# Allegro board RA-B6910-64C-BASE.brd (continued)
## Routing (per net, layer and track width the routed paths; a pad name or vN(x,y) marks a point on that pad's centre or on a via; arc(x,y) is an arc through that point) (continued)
FAN0_SDA: length 236.5
  TOP w0.201: v2(96.74,158.53) 96,157.79 96,156.87 96.33,156.54 R227.2 96.99,156.54 97.27,156.26 97.27,152.83 97.6,152.5 97.6,151.79 97.37,151.56 U8.4
  SIG2 w0.16: J2.13 309.61,165.28 304.03,165.28 303.05,166.26 217.94,166.26 214.48,162.8 182.87,162.8 180.13,165.55 157.77,165.55 156,167.32 145.61,167.32 144.23,165.95 139.03,165.95 129.38,156.3 123.89,156.3 121.4,158.79 112.25,158.79 111.43,157.97 97.85,157.97 97.3,158.53 v2(96.74,158.53)
FAN0_TACH: length 218.9
  TOP w0.201: Q11.3 132.93,120.2 132.55,120.58 R277.2 131.66,120.68 132.62,121.63 132.62,124.86 v1(132.77,125.01) 132.97,125.21 U1.33 ; R311.2 v2(314.72,166.32)
  SIG1 w0.15: v2(314.72,166.32) 311.96,166.32 293.82,148.18 166.32,148.18 143.93,125.79 133.55,125.79 v1(132.77,125.01)
FAN0_TACH_RESERVE: length 11.1
  TOP w0.508: v2(327.01,170.74) R331.1 R329.1 328.18,172.49 328.16,172.52 R330.1
  SIG1 w0.508: v2(327.01,170.74) 324.68,168.41 J2.16
FAN0_TACH_RESERVE_CPLD: length 224
  TOP w0.201: U1.76 v1(132.97,147.26)
  TOP w0.508: R330.2 R328.2 331.74,174.02 332.22,173.54 Q14.3 v2(331.08,172.65)
  SIG2 w0.508: v1(132.97,147.26) 132.97,147.38 139.96,154.36 139.96,155.75 150.01,165.81 155.37,165.81 157.14,164.04 179.49,164.04 182.24,161.29 206.03,161.29 206.77,160.55 211.94,160.55 212.68,161.29 215.11,161.29 218.57,164.75 302.27,164.75 305.35,161.67 316.17,161.67 326.25,171.76 330.19,171.76 v2(331.08,172.65)
FAN1_E2_WP: length 119.3
  TOP w0.201: R6.2 v2(123.56,122.74)
  SIG1 w0.15: J4.6 210.94,169.53 210.94,163.12 211.71,162.35 211.71,161.54 203.05,152.88 165.13,152.88 143.9,131.65 130.95,131.65 129.15,129.84 124.57,129.84 122.93,128.2 122.93,124.39 123.56,123.75 v2(123.56,122.74)
FAN1_EN: length 122.9
  TOP w0.201: R326.2 125.97,122.23 v2(125.85,122.1) 125.57,121.82 R339.1
  SIG1 w0.15: v2(125.85,122.1) 125.73,122.21 125.73,125.11 126.27,125.64 126.27,126.33 127.83,127.9 128.81,127.9 131.42,130.51 144.37,130.51 165.29,151.43 203.39,151.43 219.27,167.31 220.46,167.31 221.22,168.07 221.22,169.65 J4.2
FAN1_LED1: length 114
  TOP w0.201: v2(123.94,128.45) 123.47,127.98 U1.14
  SIG1 w0.15: v2(123.94,128.45) 124.96,129.47 129.31,129.47 131.11,131.27 144.05,131.27 165.19,152.41 203.12,152.41 213.48,162.77 213.48,169.53 J4.5
FAN1_LED2: length 108.8
  TOP w0.201: v2(126.86,128.45) 126.47,128.06 U1.20
  SIG1 w0.15: J4.12 214.9,163.66 203.18,151.94 165.26,151.94 144.21,130.89 131.27,130.89 128.83,128.45 v2(126.86,128.45)
FAN1_POWER_OK#: length 137.4
  TOP w0.201: v2(128.02,130.81) 127.98,130.77 127.98,128.42 127.97,128.41 U1.23 127.97,125.34 R164.1 ; R100.1 240.38,169.22 240.52,169.08 240.52,166.59 239.42,165.49 214.7,165.49 212.84,163.63 210.86,163.63 v1(208.56,161.33)
  SIG1 w0.15: v2(128.02,130.81) 130.15,132.95 135.83,132.95 136.6,133.71 144.89,133.71 165.09,153.91 201.14,153.91 v1(208.56,161.33)
FAN1_PRESENT_IN#: length 136.2
  TOP w0.201: v1(129.28,130.74) 129.28,129.4 128.47,128.6 U1.24 128.47,125.1 128.13,124.77 R163.1 ; R99.1 241.06,166.42 239.63,164.98 215.72,164.98 213.86,163.13 211.38,163.13 v2(209.6,161.34)
  SIG1 w0.15: v2(209.6,161.34) 201.61,153.35 165.06,153.35 145.05,133.34 136.76,133.34 135.99,132.57 131.11,132.57 v1(129.28,130.74)
FAN1_PWM: length 114.2
  TOP w0.201: U1.21 v2(126.97,126.02)
  SIG1 w0.15: v2(126.97,126.02) 127.46,126.02 131.58,130.13 144.53,130.13 165.31,150.92 203.42,150.92 219.43,166.93 221.04,166.93 J4.15
FAN1_SCL: length 148.7
  TOP w0.201: v2(97.85,159.18) 97.22,159.82 94.35,159.82 93.59,159.06 93.59,156.9 94.12,156.37 94.12,154.21 94.45,153.88 R230.2 94.99,153.27 95.57,152.69 95.57,151.89 95.42,151.75 U8.7
  SIG2 w0.16: J4.4 218.68,169.71 218.68,167.95 214.21,163.47 183.16,163.47 180.41,166.22 158.04,166.22 156.27,167.99 145.33,167.99 143.96,166.62 138.76,166.62 129.1,156.96 124.17,156.96 121.67,159.46 106.73,159.46 105.91,158.64 98.39,158.64 v2(97.85,159.18)
FAN1_SDA: length 143.6
  TOP w0.201: v2(94.35,157.91) 94.35,157.18 94.99,156.54 R229.2 95.6,156.54 96,156.14 96,154.99 95.75,154.74 95.75,153.47 96,153.22 96,151.95 96.07,151.87 U8.6
  SIG2 w0.16: v2(94.35,157.91) 93.97,158.3 93.97,159.48 94.31,159.82 98.16,159.82 98.67,159.31 105.63,159.31 106.45,160.13 121.95,160.13 124.45,157.63 128.83,157.63 138.48,167.28 143.68,167.28 145.05,168.65 156.55,168.65 158.32,166.88 180.71,166.88 183.45,164.14 213.17,164.14 J4.13
FAN1_TACH: length 136.7
  TOP w0.201: v1(126.75,130.81) 127.47,130.09 U1.22 ; R312.2 239.87,166.65 239.51,166.3 233.16,166.3 232.78,166.68 Q12.3 231.23,168.07 230.85,167.69 R280.2 230.85,166.42 230.42,165.99 214.49,165.99 212.63,164.14 210.35,164.14 v2(207.52,161.31)
  SIG1 w0.15: v2(207.52,161.31) 200.5,154.29 164.93,154.29 144.74,134.09 129.79,134.09 126.75,131.05 v1(126.75,130.81)
FAN1_TACH_RESERVE: length 12.7
  TOP w0.508: v2(232.4,173.54) R349.1 R347.1 233.31,175.29 233.29,175.31 R348.1
  SIG1 w0.508: v2(232.4,173.54) 227.27,168.41 J4.16
FAN1_TACH_RESERVE_CPLD: length 130
  TOP w0.201: v1(133.97,147.25) 133.47,147.75 U1.75
  TOP w0.508: R348.2 R346.2 236.74,176.81 237.35,176.2 Q15.3 v2(236.08,175.44)
  SIG1 w0.508: v2(236.08,175.44) 236.08,175.13 230.62,169.67 230.62,165.92 229.86,165.15 v1(229.86,163.88)
  SIG2 w0.508: v1(229.86,163.88) 218.76,163.88 215.42,160.54 212.99,160.54 212.25,159.8 206.46,159.8 205.72,160.54 181.93,160.54 179.18,163.29 156.83,163.29 155.06,165.06 150.32,165.06 140.71,155.44 140.71,154.05 133.97,147.32 v1(133.97,147.25)
FAN2_E2_WP: length 98.3
  TOP w0.201: R31.2 117.95,123.4 117.82,123.52 v2(117.82,123.95)
  SIG1 w0.15: J5.6 118.12,172.01 130.29,172.01 131.05,171.25 131.05,163.88 137.42,157.52 138.57,157.52 149.98,146.11 149.98,140.41 146.2,136.63 138.09,136.63 136.51,135.05 122.03,135.05 120.82,133.85 120.82,129.32 119.5,128 119.5,126.28 117.82,124.61 v2(117.82,123.95)
FAN2_EN: length 86.6
  TOP w0.201: R345.1 R325.2 116.8,123.4 116.45,123.75 116.45,124.82 v2(117.02,125.39)
  SIG1 w0.15: J5.2 128.51,169.66 128.51,165.89 137.26,157.14 138.41,157.14 149.59,145.97 149.59,140.55 146.64,137.61 138.13,137.61 136.1,135.57 121.75,135.57 120.12,133.95 120.12,129.16 117.85,126.88 117.85,126.22 v2(117.02,125.39)
FAN2_LED1: length 85.4
  TOP w0.201: v2(118.9,128.58) 118.47,128.15 U1.4
  SIG1 w0.15: v2(118.9,128.58) 118.9,129.86 119.37,130.33 119.37,134.26 121.43,136.33 135.78,136.33 137.82,138.36 146.33,138.36 148.83,140.87 148.83,145.65 138.1,156.39 136.95,156.39 127.25,166.09 122.46,166.09 120.89,167.65 120.89,169.66 J5.5
FAN2_LED2: length 82.9
  TOP w0.201: U1.2 117.47,128.2 117.48,128.21 v2(117.48,128.52)
  SIG1 w0.15: v2(117.48,128.52) 117.72,128.77 117.72,129.21 118.99,130.48 118.99,134.42 121.28,136.71 135.63,136.71 137.66,138.74 146.17,138.74 148.45,141.02 148.45,145.5 137.94,156.01 136.79,156.01 127.09,165.71 122.3,165.71 J5.12
FAN2_POWER_OK#: length 38.9
  TOP w0.201: R103.1 111.24,154.39 113.18,152.45 113.18,150.13 114.58,148.73 115.48,148.73 122.77,141.44 v1(122.77,130.12) 121.47,128.83 U1.10 121.47,126.3 121.02,125.85 R167.1
  BOTTOM w0.201: v3(123.7,130.05) 122.84,130.05 v1(122.77,130.12)
FAN2_PRESENT_IN#: length 42.8
  TOP w0.201: R166.1 119.52,121.82 119.12,122.23 119.12,125.78 119.47,126.14 U1.6 119.47,129.01 v1(121.4,130.95) 121.76,131.3 121.76,141.02 115.12,147.65 114.23,147.65 112,149.88 112,152.2 109.21,154.99 R102.1
  BOTTOM w0.201: v1(121.4,130.95) 120.9,131.44 v3(120.52,131.44)
FAN2_PWM: length 78.6
  TOP w0.201: U1.1 116.97,128.65 118.04,129.72 v2(119.5,129.72)
  SIG1 w0.15: J5.15 127.22,166.65 137.1,156.76 138.26,156.76 149.21,145.81 149.21,140.71 146.49,137.99 137.98,137.99 135.94,135.95 121.59,135.95 119.75,134.11 119.75,129.97 v2(119.5,129.72)
FAN2_SCL: length 50.3
  TOP w0.201: v2(90.29,154.46) 90.87,153.88 R232.2 92.7,152.83 94.12,151.41 U8.9
  SIG2 w0.16: v2(90.29,154.46) 89.52,155.22 89.52,159.48 93.45,163.41 103.08,163.41 105.08,165.41 116.32,165.41 118.35,167.44 118.35,169.34 118.8,169.79 120.2,169.79 121.36,170.95 J5.4
FAN2_SDA: length 47.7
  TOP w0.201: U8.8 94.77,152.41 93.41,153.78 93.41,156.06 92.93,156.54 R231.2 90.39,156.54 v2(90.26,156.54)
  SIG2 w0.16: J5.13 118.07,164.34 106.49,164.34 104.89,162.74 93.73,162.74 90.26,159.27 v2(90.26,156.54)
FAN2_TACH: length 46.7
  TOP w0.201: R283.2 110.23,154.69 112.51,152.41 v1(112.51,152.07) 112.51,150.09 114.42,148.18 115.31,148.18 122.26,141.23 122.26,130.71 120.97,129.42 U1.9 ; v2(110.99,152.07) 108.96,154.1 108.07,154.1 107.3,154.87 Q13.3 107.3,157.71 106.46,158.55 R313.2
  SIG1 w0.15: v2(110.99,152.07) v1(112.51,152.07)
FAN2_TACH_RESERVE: length 10.7
  TOP w0.508: R353.1 138.55,165.79 138.52,165.76 R352.1 R354.1 136.77,166.17 v2(135.63,167.31)
  SIG2 w0.508: v2(135.63,167.31) 134.53,168.41 J5.16
FAN2_TACH_RESERVE_CPLD: length 21
  TOP w0.201: U1.74 133.97,149.41 v1(133.47,149.91)
  TOP w0.508: R353.2 R351.2 140.05,162.21 139.56,161.72 Q16.3 v2(138.67,160.71)
  SIG2 w0.508: v2(138.67,160.71) 138.67,157.41 137.91,156.64 137.91,153.87 133.96,149.91 v1(133.47,149.91)
GPIO_I2C_SCL: length 199
  TOP w0.127: U9.B27 v1(163.8,68.15)
  TOP w0.201: R268.1 140.48,132.9 138.85,132.9 137.65,134.1 U1.47 135.03,134.1 133.75,132.82 132.44,132.82 131.62,132 v2(131.62,128.4) ; v1(94.33,90.35) YJ1.A8_1
  SIG2 w0.16: v2(131.62,128.4) 131.62,127.9 130.36,126.64 110.36,126.64 110.05,126.33 103.88,126.33 103.19,125.64 99.46,125.64 98.83,125.01 95.21,125.01 91.54,121.35 89.05,121.35 85.18,117.49 79.58,117.49 73.95,111.86 73.95,100.55 84.16,90.35 v1(94.33,90.35) 97.4,90.35 99.02,88.73 122.82,88.73 139.75,71.81 149.34,71.81 153.85,67.3 162.94,67.3 v1(163.8,68.15)
GPIO_I2C_SDA: length 206.4
  TOP w0.127: U9.B28 v1(165.07,65.61)
  TOP w0.201: YJ1.A7_1 95.58,94.67 95.92,94.33 95.92,90.62 v1(94.99,89.68) ; v2(141.51,132.69) 141.51,132.87 141.37,133.01 R270.1 R269.2
  SIG2 w0.16: v2(141.51,132.69) 138.8,129.97 131.94,129.97 130.95,128.98 130.95,128.18 130.08,127.31 110.1,127.31 109.72,127.69 108.19,127.69 107.61,127.1 103.65,127.1 102.86,126.31 96.54,126.31 95.92,125.68 94.93,125.68 92.6,123.35 84.49,123.35 73.28,112.14 73.28,100.28 83.88,89.68 v1(94.99,89.68) 97.12,89.68 98.74,88.06 122.54,88.06 139.71,70.9 148.83,70.9 153.34,66.39 164.3,66.39 v1(165.07,65.61)
LM75_INT#: length 75.8
  TOP w0.201: R118.1 113.07,130.99 114.18,132.1 U1.138 116.16,132.1 116.45,132.39 116.45,133.03 117.08,133.66 v1(121.27,133.66) ; R221.1 v2(142.67,169.39)
  SIG1 w0.15: v2(142.67,169.39) 142.67,153.95 150.36,146.27 150.36,140.25 144.58,134.47 122.09,134.47 v1(121.27,133.66)
LPC_LAD0: length 93.9
  TOP w0.201: v1(147.19,141.3) 146.93,141.03 146.93,139.5 143.95,136.52 141.65,136.52 141.17,136.05 140.49,136.05 140.39,135.94 R126.2 ; v1(167.37,72.6) U9.A23
  SIG1 w0.15: v2(167.99,125.76) 168.91,124.84 168.91,121.96 169.45,121.42 169.45,74.68 v1(167.37,72.6)
  SIG2 w0.16: v1(147.19,141.3) 152.45,141.3 v2(167.99,125.76)
LPC_LAD0_CPLD: length 119.9
  TOP w0.201: C142.1 89.27,95.94 89.83,95.38 YJ1.A2_1 ; R314.2 144.75,127.94 146.16,126.53 146.16,121.16 v2(133.14,108.13)
  SIG2 w0.16: YJ1.A2_1 89.36,93.27 82.67,99.96 82.67,107.83 86.48,111.64 90.93,111.64 98.45,119.16 101.19,119.16 101.87,119.84 113.04,119.84 124.29,108.59 132.67,108.59 v2(133.14,108.13)
LPC_LAD1: length 95.7
  TOP w0.201: v2(146.15,141.28) 146.15,139.99 143.25,137.09 R129.2 ; U9.A26 v1(167.37,68.79)
  SIG1 w0.15: v1(167.37,68.79) 169.92,71.34 169.92,121.62 v1(169.38,122.16)
  SIG2 w0.16: v2(146.15,141.28) 146.63,141.76 152.64,141.76 168.5,125.89 168.5,123.04 v1(169.38,122.16)
LPC_LAD1_CPLD: length 109
  TOP w0.201: R315.2 144.5,126.93 145.27,126.16 145.27,122.34 v2(131.05,108.13) ; C143.1 78.35,96.95 78.46,97.07 YJ1.B2_1
  SIG2 w0.16: v2(131.05,108.13) 124.18,108.13 113.43,118.88 101.47,118.88 101.36,118.76 98.61,118.76 91.07,111.22 86.65,111.22 83.09,107.66 83.09,103.59 89.61,97.07 YJ1.B2_1
LPC_LAD2: length 102.7
  TOP w0.127: U9.A29 v1(166.34,64.34)
  TOP w0.201: R132.2 140.32,138.23 140.86,138.76 142.51,138.76 144.13,140.39 v1(144.13,141.28)
  SIG1 w0.15: v1(166.34,64.34) 170.39,68.4 170.39,122.93 v2(169.38,123.94)
  SIG2 w0.16: v1(144.13,141.28) 145.02,142.17 152.8,142.17 168.9,126.06 168.9,124.42 v2(169.38,123.94)
LPC_LAD2_CPLD: length 112.2
  TOP w0.201: C144.1 88.45,99.49 YJ1.C2_1 ; v2(133.23,106.72) 133.47,106.72 147.52,120.77 147.52,127.94 145.49,129.97 R316.2
  SIG2 w0.16: v2(133.23,106.72) 132.68,106.17 125,106.17 113.89,117.29 98.28,117.29 91.4,110.42 86.98,110.42 83.89,107.32 83.89,104.23 87.25,100.87 YJ1.C2_1
LPC_LAD3: length 105.7
  TOP w0.127: U9.B30 v1(165.07,63.07)
  TOP w0.201: v2(144.16,142.32) 143.51,141.67 143.51,140.48 142.4,139.37 140.83,139.37 140.71,139.25 R134.2
  SIG1 w0.15: v1(169.38,125.72) 170.86,124.24 170.86,68.18 166.36,63.68 165.68,63.68 v1(165.07,63.07)
  SIG2 w0.16: v2(144.16,142.32) 144.42,142.57 152.96,142.57 169.38,126.15 v1(169.38,125.72)
LPC_LAD3_CPLD: length 114.9
  TOP w0.201: YJ1.B1_1 78.98,98.47 78.48,97.97 C145.1 ; R317.2 145.49,130.99 148.02,128.45 148.02,120.56 133.68,106.22 131.54,106.22 v2(131.05,106.7)
  SIG2 w0.16: v2(131.05,106.7) 125.04,106.7 113.5,118.24 105.79,118.24 105.23,117.69 98.11,117.69 91.24,110.82 86.82,110.82 83.49,107.49 83.49,104.06 YJ1.B1_1
LPC_LCLK: length 76.5
  TOP w0.201: U9.A14 v1(167.37,84.03) ; R136.2 140.58,140.26 140.83,140.52 141.7,140.52 v2(142.21,140.01)
  SIG1 w0.15: v1(166.72,123.99) 166.72,121.84 167.81,120.74 167.81,84.48 v1(167.37,84.03)
  SIG2 w0.16: v2(142.21,140.01) 142.53,139.68 151.86,139.68 166.05,125.49 166.05,124.66 v1(166.72,123.99)
LPC_LCLK_CPLD: length 106.6
  TOP w0.201: R320.2 145.49,132.01 148.71,128.79 148.71,120.53 133.89,105.71 132.06,105.71 v2(131.05,104.7) ; YJ1.C1_1 87.55,100.74 78.21,100.74 77.98,100.51 C146.1
  SIG2 w0.16: v2(131.05,104.7) 125.91,104.7 113.72,116.89 98.44,116.89 88.31,106.75 88.31,104.52 89.08,103.75 YJ1.C1_1
LPC_LFRAME#: length 86.2
  TOP w0.201: R137.2 139.92,141.28 142.55,141.28 v1(143,140.82) ; v1(167.37,76.41) U9.A20
  SIG1 w0.15: v1(167.37,76.41) 168.98,78.02 168.98,121.23 167.99,122.22 v2(167.99,123.98)
  SIG2 w0.16: v2(167.99,123.98) 167.5,124.46 167.5,125.64 152.37,140.77 143.54,140.77 143.48,140.82 v1(143,140.82)
LPC_LFRAME#_CPLD: length 105.1
  TOP w0.201: v2(132.45,104.7) 132.96,105.21 134.1,105.21 149.21,120.32 149.21,129.17 145.36,133.02 R322.2 ; YJ1.D1_1 88.9,105.89 88.9,104.52 86.92,102.54 C147.1
  SIG2 w0.16: YJ1.D1_1 89.08,106.96 98.61,116.49 113.55,116.49 125.8,104.24 131.99,104.24 v2(132.45,104.7)
LPC_SERIRQ: length 83.4
  TOP w0.201: R139.2 142.67,142.29 v2(142.78,142.18) ; U9.A17 v1(167.37,80.22)
  SIG1 w0.15: v1(166.72,125.77) 167.51,124.98 167.51,122.03 168.51,121.03 168.51,81.36 v1(167.37,80.22)
  SIG2 w0.16: v1(166.72,125.77) 166.72,125.77 152.12,140.36 142.8,140.36 142.49,140.67 142.49,141.9 v2(142.78,142.18)
LPC_SERIRQ_CPLD: length 111.4
  TOP w0.201: v2(133.64,104.7) 134.31,104.7 149.72,120.11 149.72,131.12 145.91,134.93 R324.2 ; C148.1 86.69,101.53 YJ1.D2_1
  SIG2 w0.16: YJ1.D2_1 89.83,107.14 98.78,116.08 113.36,116.08 125.61,103.84 132.78,103.84 v2(133.64,104.7)
MDI_0N: length 275.7
  TOP w0.127: U9.A32 v1(166.34,60.53)
  SIG2 w0.104: J10.2 407.04,4.06 407.04,4.74 406.49,5.3 406.49,6.57 406.55,6.64 406.55,6.67
  SIG2 w0.13: 406.55,6.67 406.55,7.76 392.29,22.02 388.38,22.02 343.5,66.9 171.05,66.9 168.07,63.91 165.93,63.91 165.51,63.5 165.51,61.26 165.9,60.88 166.21,60.88 166.34,60.75 v1(166.34,60.53)
MDI_0P: length 275.7
  TOP w0.127: U9.A31 v1(166.34,61.8)
  SIG2 w0.104: J10.3 405.35,5.05 406.29,4.11 406.43,4.11 406.77,4.45 406.77,4.63 406.22,5.18 406.22,6.57 406.15,6.64 406.15,6.67
  SIG2 w0.13: 406.15,6.67 406.15,7.59 392.12,21.62 388.21,21.62 343.34,66.49 171.22,66.49 168.24,63.51 166.1,63.51 165.92,63.33 165.92,61.43 166.07,61.28 166.26,61.28 166.34,61.36 v1(166.34,61.8)
MDI_1N: length 272.5
  TOP w0.127: U9.C32 v1(162.53,60.53)
  SIG2 w0.104: J10.5 403.35,4.6 403.43,4.52 404.12,4.52 404.22,4.62 404.22,6.6 404.15,6.67 404.15,6.69
  SIG2 w0.13: 404.15,6.69 404.15,7.37 391.56,19.96 387.11,19.96 344.39,62.68 170.71,62.68 167.73,59.7 164.31,59.7 162.99,61.02 162.66,61.02 162.53,60.89 v1(162.53,60.53)
MDI_1P: length 272.5
  TOP w0.127: U9.C31 v1(162.53,61.8)
  SIG2 w0.104: 404.56,6.69 404.56,6.67 404.49,6.6 404.49,4.51 404.23,4.25 403.85,4.25 J10.6
  SIG2 w0.13: v1(162.53,61.8) 162.53,61.58 162.68,61.42 163.16,61.42 164.48,60.1 167.56,60.1 170.54,63.09 344.56,63.09 387.28,20.37 391.73,20.37 404.56,7.53 404.56,6.69
MDI_2N: length 266.2
  TOP w0.127: U9.A35 v1(166.34,56.72)
  SIG2 w0.104: J10.8 400.49,4.61 400.49,6.65 400.56,6.72 400.56,6.75
  SIG2 w0.13: 400.56,6.75 400.56,8.43 390.74,18.24 385.68,18.24 342.76,61.17 170.91,61.17 168.58,58.83 165.92,58.83 165.51,58.43 165.51,57.45 165.91,57.05 166.21,57.05 166.34,56.93 v1(166.34,56.72)
MDI_2P: length 266.2
  TOP w0.127: U9.A34 v1(166.34,57.99)
  SIG2 w0.104: J10.9 398.87,5.75 398.59,5.47 398.59,4.83 398.73,4.69 400.08,4.69 400.22,4.83 400.22,6.65 400.15,6.72 400.15,6.75
  SIG2 w0.13: 400.15,6.75 400.15,8.26 390.58,17.83 385.51,17.83 342.59,60.76 171.08,60.76 168.74,58.43 166.09,58.43 165.92,58.26 165.92,57.62 166.08,57.46 166.21,57.46 166.34,57.59 v1(166.34,57.99)
MDI_3N: length 265.5
  TOP w0.127: U9.C35 v1(162.53,56.72)
  SIG2 w0.104: 396.56,6.78 396.56,6.76 396.49,6.69 396.49,4.99 396.62,4.86 397.25,4.86 397.35,4.97 J10.11
  SIG2 w0.13: 396.56,6.78 396.56,9.25 389.75,16.06 383.85,16.06 340.63,59.28 171.31,59.28 168.32,56.29 162.28,56.29 162.09,56.49 162.09,57.33 162.22,57.46 162.42,57.46 162.53,57.35 v1(162.53,56.72)
MDI_3P: length 265.5
  TOP w0.127: U9.C34 v1(162.53,57.99)
  SIG2 w0.104: 396.16,6.78 396.16,6.76 396.22,6.69 396.22,4.88 J10.12
  SIG2 w0.13: 396.16,6.78 396.16,7.27 396.16,9.08 389.58,15.65 383.68,15.65 340.46,58.87 171.48,58.87 168.49,55.89 162.11,55.89 161.68,56.32 161.68,57.5 162.05,57.87 162.4,57.87 v1(162.53,57.99)
MGMT LED_ACT: length 148.8
  TOP w0.127: v1(165.07,55.48) 164.46,56.09 U9.B36
  TOP w0.201: v1(117.1,132.88) 117.1,131.6 116.1,130.6 U1.141
  SIG1 w0.15: v2(173.22,125.94) 172.11,125.94 171.33,125.17 171.33,60.78 166.66,56.1 165.69,56.1 v1(165.07,55.48)
  SIG2 w0.16: v1(117.1,132.88) 117.1,133.25 123.35,139.5 137.61,139.5 142.97,144.86 154.3,144.86 v2(173.22,125.94)
MGMT LED_LINK_100: length 149.7
  TOP w0.127: U9.A37 v1(166.34,54.18)
  TOP w0.201: U1.143 116.66,129.6 118.39,131.33 v1(118.39,132.17)
  SIG1 w0.15: v2(173.22,124.13) 172.28,123.19 172.28,60.65 167.45,55.82 167.45,55.39 166.34,54.28 v1(166.34,54.18)
  SIG2 w0.16: v1(118.39,132.17) 117.85,132.17 117.62,132.4 117.62,133.18 123.43,138.99 137.73,138.99 143.2,144.45 154.14,144.45 172.76,125.84 172.76,124.59 v2(173.22,124.13)
MGMT LED_LINK_1000: length 148.7
  TOP w0.127: U9.A38 v1(166.34,52.91)
  TOP w0.201: U1.142 116.32,130.1 117.67,131.45 117.67,132.34 v1(118.39,133.06)
  SIG1 w0.15: v1(166.34,52.91) 166.98,52.91 168.45,54.39 168.45,55.75 173.51,60.82 173.51,122.49 v2(173.22,122.78)
  SIG2 w0.16: v2(173.22,122.78) 173.22,123.4 172.09,124.53 172.09,125.93 153.98,144.05 143.42,144.05 137.86,138.48 123.81,138.48 v1(118.39,133.06)
MGMT_LED_GREEN: length 369
  TOP w0.201: U1.97 122.47,147.58 123.31,146.74 v1(123.31,146.1) ; J10.24 384.35,4.75 384.35,8.81 380.46,12.69 C129.1 379.5,13.74 378.96,14.28 378.96,34.47 v2(378.32,35.11)
  SIG1 w0.15: v1(144.49,145.97) 123.44,145.97 v1(123.31,146.1) ; v1(176.01,122.2) 176.71,122.2 177.38,121.54 v1(177.38,102.42)
  SIG2 w0.16: v2(378.32,35.11) 377.05,36.38 344.74,68.69 184.29,68.69 177.86,75.12 177.86,101.94 v1(177.38,102.42) ; v1(176.01,122.2) 176.84,123.03 176.84,125.22 155.44,146.62 145.14,146.62 v1(144.49,145.97)
MGMT_LED_LINKACT: length 371.3
  TOP w0.201: v1(122.04,146.1) 121.97,146.17 U1.98 ; J10.26 382.13,4.97 382.13,7.97 378.18,11.92 C130.1 377.18,13.74 376.54,14.37 376.54,15.17 378.32,16.94 v2(378.32,33.78)
  SIG1 w0.15: v1(143.85,145.34) 143.59,145.6 122.54,145.6 v1(122.04,146.1) ; v1(177.38,100.64) 176.9,101.11 v1(176.9,121.34)
  SIG2 w0.16: v2(378.32,33.78) 378.32,34.22 344.48,68.06 184.28,68.06 177.38,74.97 v1(177.38,100.64) ; v1(143.85,145.34) 143.85,146.07 144.8,147.03 155.62,147.03 177.24,125.4 177.24,122.7 176.9,122.35 v1(176.9,121.34)
MOD_PRE0: length 70.1
  TOP w0.127: U9.D38 v1(161.26,52.91)
  TOP w0.201: U9.A1 176.11,100.54 176.39,100.26 176.39,98.22 v2(175,96.83)
  SIG1 w0.15: v1(161.26,52.91) 162.11,52.06 167.39,52.06 169.21,53.88 169.21,55.44 174.64,60.88 174.64,96.48 v2(175,96.83)
ONLINE_CPLD_UPDATE1: length 136.2
  TOP w0.201: U2.11 56.75,90.23 56.25,90.73 R153.1 55.46,91.34 55.62,91.49 57.74,91.49 63.98,97.73 64.65,97.73 65.65,98.73 v2(66.16,98.73) ; U9.B7 v1(163.8,93.55)
  SIG1 w0.15: v1(77.84,104.96) 77.45,104.96 71.86,99.37 66.79,99.37 v2(66.16,98.73)
  SIG2 w0.16: v1(77.84,104.96) 85.78,112.89 87.21,112.89 91.07,116.75 93.46,116.75 97.13,120.42 100.74,120.42 101.37,121.04 113.54,121.04 124.79,109.8 133.45,109.8 145.4,97.84 157.47,97.84 161.76,93.55 v1(163.8,93.55)
ONLINE_CPLD_UPDATE2: length 56.9
  TOP w0.201: YJ1.C1_2 100.33,103.02 100.33,106.98 v2(92.06,115.24) ; R156.2 C138.1 68.6,90.63 68.82,90.86 70.9,90.86 v1(71.66,90.1)
  SIG1 w0.15: v2(92.06,115.24) 90.6,113.78 88.02,113.78 81.48,107.23 81.48,100.45 71.66,90.64 v1(71.66,90.1)
ONLINE_TCK: length 56
  TOP w0.201: v2(89.78,114.82) 89.78,114.09 95.76,108.12 95.76,104.39 99.28,100.87 YJ1.C2_2 ; v1(68.95,93.22) 68.75,93.22 68.19,93.78 C136.1 R147.2
  SIG1 w0.15: v2(89.78,114.82) 87.59,114.82 80.33,107.55 80.33,102.53 79.32,101.53 78.36,101.53 69.93,93.1 69.07,93.1 v1(68.95,93.22)
ONLINE_TDI: length 64.5
  TOP w0.201: R255.2 C134.1 56.56,88.7 56.78,88.93 U2.13 59.27,88.93 59.63,89.29 59.63,91.96 63.74,96.07 v1(67.06,96.07) ; v2(89.5,81.85) 90.93,81.85 100.07,90.99 100.07,91.51 YJ1.A2_2
  SIG2 w0.16: v2(89.5,81.85) 80.77,81.85 76.33,86.29 74.12,86.29 68.27,92.14 68.27,93.38 67.06,94.58 v1(67.06,96.07)
ONLINE_TDO: length 47.2
  TOP w0.201: YJ1.B2_2 101.32,97.07 96.93,92.68 96.93,90.2 88.9,82.17 88.9,81.15 88.14,80.39 v2(88.14,79.88) ; v1(69.59,85.02) 68.6,86.01 C135.1 R152.2
  SIG2 w0.16: v2(88.14,79.88) 87.58,80.44 80.51,80.44 75.94,85.02 v1(69.59,85.02)
ONLINE_TMS: length 56.9
  TOP w0.201: v2(88.13,81.33) 88.13,82.11 96.43,90.41 96.43,93.82 YJ1.B1_2 ; v1(67.05,98.73) 67.4,98.38 C137.1 R149.2
  SIG2 w0.16: v1(67.05,98.73) 66.41,98.1 66.41,94.67 67.81,93.27 67.81,91.95 73.93,85.83 76.14,85.83 80.52,81.45 88.02,81.45 v2(88.13,81.33)
PCA9641_RST#: length 15.9
  TOP w0.201: v2(110.12,129.97) R58.2 ; U10.4 102.04,132.7 102.22,132.51 R297.2 103.52,133.1 103.74,133.31 105.36,133.31 105.78,132.9 105.78,128.83 v1(106.16,128.45)
  SIG1 w0.15: v1(106.16,128.45) 108.6,128.45 v2(110.12,129.97)
PCA9641_SCL: length 238.1
  TOP w0.201: v1(86.48,133.66) 87.44,132.69 89.19,132.69 89.63,133.12 R306.2 90.03,133.53 90.41,133.15 R300.2 ; U7.2 v2(144.83,171.66) ; YJ1.A8_2 104.94,91.88 101.97,91.88 v1(93.2,83.12) ; U8.22 v1(98.02,143.45) ; U1.68 137.93,144.6 138.42,145.09 R271.1 138.95,144.43 139.18,144.2 140.71,144.2 141.47,144.96 142.74,144.96 143.25,145.47 143.25,147.23 142.07,148.4 142.07,154.12 141,155.19 129.32,155.19 125.81,158.7 v1(125.47,158.7)
  SIG2 w0.16: v1(93.2,83.12) 92.6,82.51 82.77,82.51 67.79,97.5 67.79,114.97 83.75,130.93 84.61,131.79 85.57,131.79 86.46,132.68 86.46,133.64 v1(86.48,133.66) 86.48,135.02 89.14,137.69 89.14,138.37 90.81,140.04 97.15,140.04 97.65,140.54 97.65,143.08 v1(98.02,143.45) 98.02,144.15 91.02,151.15 91.02,159.08 92.82,160.89 98.6,160.89 99.11,160.38 105.19,160.38 106.01,161.2 122.84,161.2 125.34,158.7 v1(125.47,158.7) 128.38,158.7 138.04,168.35 143.24,168.35 144.27,169.39 144.27,171.1 v2(144.83,171.66)
PCA9641_SDA: length 236.7
  TOP w0.201: v1(124.62,158.3) 125.13,157.79 125.72,157.79 129.02,154.49 140.71,154.49 141.37,153.82 R273.1 140.71,145.72 140.32,146.1 R272.2 ; YJ1.A7_2 104.44,95.81 100.78,95.81 97.44,92.47 97.44,89.18 v1(91.43,83.18) ; v1(88.25,130.61) 88.25,131.75 88.48,131.98 R304.2 89.49,131.98 89.89,132.39 91.33,132.39 R302.2 ; R219.1 v2(142.67,171.68) ; R239.1 98.92,140.77 v1(99.05,140.64)
  SIG2 w0.16: v1(91.43,83.18) 83.05,83.18 68.46,97.77 68.46,114.55 84.29,130.38 84.52,130.61 v1(88.25,130.61) 88.25,130.99 87.16,132.09 87.16,134.75 89.93,137.53 89.93,138.21 91.05,139.33 98.24,139.33 99.05,140.13 v1(99.05,140.64) 98.92,140.77 98.92,144.2 91.68,151.44 91.68,158.8 93.1,160.22 98.33,160.22 98.84,159.71 105.46,159.71 106.28,160.53 122.38,160.53 v1(124.62,158.3) 124.88,158.03 128.66,158.03 138.31,167.69 143.51,167.69 145.68,169.85 145.68,171.86 145.15,172.39 143.39,172.39 v2(142.67,171.68)
PCIE_COFIG: length 20.9
  TOP w0.201: U9.C23 162.56,71.99 156.14,71.99 152.32,75.81 149.1,75.81 148.59,76.33 v1(146.81,76.33) 146.3,75.81 R259.2
  BOTTOM w0.201: v3(146.81,75.44) v1(146.81,76.33)
PCIE_REFCLK_N: length 89.2
  TOP w0.127: U9.B25 v1(165.07,69.42)
  SIG2 w0.104: YJ1.C8_1 94.33,101.22 arc(94.37,101.52) 94.49,101.79 arc(94.55,101.87) 94.62,101.95 arc(94.63,101.97) 94.64,101.98 arc(94.84,102.12) 95.07,102.16 95.62,102.16 96.1,101.68 96.1,101.58 96.12,101.57
  SIG2 w0.13: 96.12,101.57 97,100.68 97,95.51 101.8,90.71 122.49,90.71 138.11,75.08 151.6,75.08 156.83,69.86 164.64,69.86 v1(165.07,69.42)
PCIE_REFCLK_P: length 89.2
  TOP w0.127: U9.B24 v1(165.07,70.69)
  SIG2 w0.104: 96.41,101.85 96.39,101.87 96.29,101.87 95.73,102.43 95.07,102.43 arc(94.74,102.36) 94.45,102.17 arc(94.44,102.16) 94.42,102.14 arc(94.07,101.98) 93.72,102.13 YJ1.C7_1
  SIG2 w0.13: 96.41,101.85 97.41,100.85 97.41,95.67 101.97,91.11 122.66,91.11 138.28,75.49 151.76,75.49 156.99,70.26 164.77,70.26 165.07,70.56 v1(165.07,70.69)
PSON1: length 11.5
  TOP w0.201: v1(372.55,118.43) 372.34,118.65 R2.2 371.97,119.22 371.97,120.4 R174.2 C78.2 372.54,121.51 372.78,121.75 372.78,123.1 373.2,123.52 J8.A21
  BOTTOM w0.201: v1(372.55,118.43) 372.62,118.49 v3(373.63,118.49)
PSON2: length 9.5
  TOP w0.201: J9.A21 17.2,125.62 C90.2 17.59,121.11 17.8,120.9 17.8,119.04 R183.2 R1.2
PULL_UP_3.3V_PWR1: length 29.5
  TOP w0.201: v1(92.7,140.64) 92.57,140.77 R236.1 R235.1 ; v2(104.06,148.08) 106.9,150.93 D2.2 109.15,149.85 108.47,149.18 R135.2
  SIG1 w0.15: v2(104.06,148.08) 100.2,148.08 95.46,143.34 95.46,140.32 94.9,139.75 93.59,139.75 v1(92.7,140.64)
PULL_UP_3.3V_PWR2: length 29.5
  TOP w0.201: v1(94.99,140.52) R238.1 R237.1 ; R138.2 111.14,149.89 111.05,149.98 D2.1 110.35,150.93 110.1,151.18 110.1,151.69 109.84,151.95 106.72,151.95 v2(104.06,149.28)
  SIG1 w0.15: v2(104.06,149.28) 100.86,149.28 94.99,143.4 v1(94.99,140.52)
PWR1_OUTPUT_OK: length 281.6
  TOP w0.201: v2(357.05,119.73) 357.68,119.1 360.22,119.1 360.86,119.73 R178.1 ; R127.1 109.44,142.64 109.61,142.47 112.82,142.47 v1(113.15,142.8) 113.35,142.6 U1.117
  SIG1 w0.15: v2(357.05,119.73) 356.29,118.97 341.61,118.97 331.21,129.37 150.2,129.37 144.46,123.63 136.16,123.63 136.16,123.62 134.05,123.62 134.03,123.6 134.03,121.92 133.7,121.59 124.32,121.59 123.81,122.1 118.78,122.1 115.85,125.03 115.85,140.69 113.74,142.8 v1(113.15,142.8)
PWR1_PRESENT#: length 282
  TOP w0.201: U1.114 v1(112.87,144.1) 112.77,144.2 C61.1 112.11,143.82 111.93,143.64 109.64,143.64 109.44,143.84 R131.2 ; v2(358.41,119.86) 358.56,120.01 R177.2
  SIG1 w0.15: v2(358.41,119.86) 356.88,118.34 341.53,118.34 331,128.86 150.23,128.86 141.3,119.94 125.44,119.94 123.65,121.72 118.62,121.72 115.38,124.97 115.38,139.05 112.64,141.79 112.64,143.87 v1(112.87,144.1)
PWR1_PSON: length 267.2
  TOP w0.201: v2(355.73,119.71) 355.73,118.41 357.75,116.39 369.43,116.39 370.73,117.68 R2.1 ; v1(147.83,145.33) 147.83,134.67 v1(152.39,130.1) ; v1(128.51,144.58) 128.51,147.37 128.97,147.83 U1.84
  SIG1 w0.15: v1(152.39,130.1) 152.74,129.75 331.37,129.75 341.77,119.35 355.36,119.35 v2(355.73,119.71) ; v1(128.51,144.58) 147.07,144.58 v1(147.83,145.33)
PWR1_SCL: length 334.1
  TOP w0.201: R236.2 92.57,143.56 92.82,143.81 U8.14 92.82,145.98 92.98,146.13 92.98,146.89 93.46,147.37 100.19,147.37 101.61,145.95 101.61,139.98 100.55,138.92 99.36,138.92 97.1,136.66 97.1,123.9 105.25,115.75 v2(105.25,115.62) ; C73.2 374.83,123.24 375.74,124.15 J8.A20
  SIG1 w0.15: v1(127.13,115.98) 127.02,115.88 112.57,115.88 111.62,116.83 106.46,116.83 v2(105.25,115.62)
  SIG2 w0.16: v1(127.13,115.98) 127.48,115.63 143.49,115.63 144.91,117.05 158.54,117.05 161.69,113.9 337.53,113.9 345.78,122.15 359.67,122.15 360.79,123.28 373.1,123.28 J8.A20
PWR1_SDA: length 338.3
  TOP w0.201: R235.2 91.56,143.49 92.17,144.1 U8.13 92.17,147.1 93.21,148.14 100.44,148.14 102.34,146.23 102.34,139.71 100.82,138.19 99.64,138.19 97.81,136.36 97.81,124.2 v1(106.39,115.62) ; C75.2 377.11,122.48 378.28,123.64 J8.A19
  SIG1 w0.15: v2(127.16,114.94) 112.18,114.94 110.99,116.13 106.9,116.13 v1(106.39,115.62)
  SIG2 w0.16: v2(127.16,114.94) 143.77,114.94 145.2,116.37 158.25,116.37 161.41,113.21 337.81,113.21 346.09,121.49 359.94,121.49 361.06,122.61 374.97,122.61 J8.A19
PWR1_SMB_ALERT#: length 289
  TOP w0.201: v2(357.68,117.32) 357.91,117.09 R175.1 ; R135.1 110.07,146.1 112.5,146.1 v1(113.2,145.4) 113.5,145.1 U1.112
  SIG1 w0.15: v1(113.2,145.4) 112.26,144.45 112.26,141.45 114.91,138.8 114.91,124.9 118.46,121.34 123.5,121.34 125.28,119.56 141.59,119.56 150.39,128.36 330.79,128.36 341.83,117.32 v2(357.68,117.32)
PWR2_OUTPUT_OK: length 140.1
  TOP w0.201: R130.1 112.7,143.06 113.25,143.6 v2(113.83,143.6) U1.115 ; R187.1 7.42,120.05 8.57,118.91 9.73,118.91 21.23,107.41 62.25,107.41 62.85,106.8 65.23,106.8 v1(66.36,107.93)
  SIG1 w0.15: v1(66.36,107.93) 66.92,107.37 67.37,107.37 80.16,120.16 89.22,120.16 92.88,123.82 92.88,128.06 94.47,129.66 94.47,133.12 98.84,137.49 101.9,137.49 105.85,141.44 107.88,141.44 109.08,142.64 109.08,145.56 109.5,145.98 113.27,145.98 113.83,145.42 v2(113.83,143.6)
PWR2_PRESENT#: length 139.9
  TOP w0.201: R186.2 6.27,119.75 6.53,119.5 7.26,119.5 8.36,118.4 9.52,118.4 21.02,106.9 62.04,106.9 62.64,106.3 65.65,106.3 v1(67.25,107.89) ; v2(107.81,146.36) 108.07,146.1 109.08,146.1 109.44,145.75 R133.2 109.44,145.01 109.61,144.83 111.88,144.83 112.11,145.06 C62.1 112.26,145.47 113.13,144.6 U1.113
  SIG1 w0.15: v2(107.81,146.36) 107.21,145.75 107.21,143.72 101.45,137.96 98.78,137.96 94.1,133.27 94.1,129.81 92.5,128.22 92.5,123.97 89.06,120.54 78.22,120.54 67.25,109.57 v1(67.25,107.89)
PWR2_PSON: length 143.9
  TOP w0.201: U1.83 v2(129.47,145.09) ; R1.1 18.34,114.88 22.57,110.65 66.01,110.65 v2(66.41,111.05)
  SIG1 w0.15: v2(66.41,111.05) 67.6,111.05 83.68,127.14 83.68,129.59 84.87,130.78 87.32,130.78 90.15,133.61 90.15,141.23 99.77,150.84 113.84,150.84 119.59,145.09 v2(129.47,145.09)
PWR2_SCL: length 112.1
  TOP w0.201: U8.16 94.12,144.15 94.99,143.28 R238.2 95.39,142.39 95.7,142.09 95.7,140.26 94.83,139.39 v1(89.5,139.39) ; J9.A20 19.44,122.05 19.99,121.5 C85.2 19.7,121.11 19.18,120.59 19.18,115.12 22.94,111.36 65.7,111.36 v1(66.41,112.07)
  SIG1 w0.15: v1(66.41,112.07) 67.68,112.07 82.41,126.8 82.41,129.97 84,131.56 87.17,131.56 89.5,133.88 v1(89.5,139.39)
PWR2_SDA: length 110.6
  TOP w0.201: v1(89.49,141.48) 90.82,140.15 93.02,140.15 93.31,140.44 93.31,141.86 R237.2 93.84,143.06 93.47,143.43 U8.15 ; J9.A19 21.98,121.81 22.15,121.64 C86.2 21.73,121.11 21.58,120.96 21.58,118.54 21.33,118.29 20.18,118.29 19.93,118.04 19.93,115.37 23.23,112.07 v1(64.63,112.07)
  SIG1 w0.15: v1(64.63,112.07) 65.39,112.83 67.51,112.83 81.4,126.71 81.4,129.97 83.64,132.22 86.9,132.22 88.84,134.15 88.84,140.82 v1(89.49,141.48)
PWR2_SMB_ALERT#: length 132.9
  TOP w0.201: U1.111 114.29,145.6 113.27,146.61 v2(112.77,146.61) 112.64,146.74 R138.1 ; v1(63.56,107.82) 62.96,108.42 21.65,108.42 10.72,119.34 R184.1
  SIG1 w0.15: v1(63.56,107.82) 65.31,109.56 66.64,109.56 80.53,123.45 91.22,123.45 92.01,124.24 92.01,128.26 93.72,129.97 93.72,133.43 98.71,138.43 101.26,138.43 106.74,143.91 106.74,146.05 107.56,146.87 108.19,146.87 108.45,146.61 v2(112.77,146.61)
SCL_R: length 29.6
  TOP w0.201: R300.1 92.83,133.15 v1(93.26,132.72) 93.28,132.7 U10.13 ; R309.1 90.03,124.68 v2(90.33,124.39) ; v1(100.83,128.04) 100.83,127.58 101.73,126.67 R307.1
  SIG1 w0.15: v2(90.33,124.39) 90.03,124.68 90.03,127.36 92.58,129.9 92.58,132.03 v1(93.26,132.72)
  SIG2 w0.16: v1(100.83,128.04) 95.4,128.04 91.49,124.13 90.59,124.13 v2(90.33,124.39)
SDA_R: length 26.4
  TOP w0.201: R308.1 103.5,128.2 v1(102.65,129.04) ; v1(91.35,124.64) 91.05,124.94 R310.1 ; U10.14 93.6,132.05 v2(93.21,131.65) 92.73,132.13 R302.1
  SIG1 w0.15: v1(91.35,124.64) 90.92,125.07 90.92,127.71 92.95,129.74 92.95,131.4 v2(93.21,131.65)
  SIG2 w0.16: v1(91.35,124.64) 91.43,124.64 95.3,128.5 102.11,128.5 v1(102.65,129.04)
SLAVE_INT#: length 55
  TOP w0.201: R267.2 122.32,152.17 v2(121.91,152.58) ; v1(90.67,131.75) 90.87,131.55 92.14,131.55 92.55,131.14 R305.1 93.21,130.74 93.87,131.4 U10.15
  SIG1 w0.15: v1(104.1,151.95) 104.13,151.92 109.14,151.92 v1(109.79,152.58)
  SIG2 w0.16: v2(121.91,152.58) 121.55,152.58 120.4,153.72 119.69,153.72 119.04,154.38 117.1,154.38 116.7,153.98 114.48,153.98 114.22,154.23 111.45,154.23 v1(109.79,152.58) ; v1(90.67,131.75) 90.67,132.39 92.45,134.17 97.02,134.17 102.93,140.08 102.93,145.91 102.35,146.48 102.35,150.19 v1(104.1,151.95)
SMI_MDC: length 19.9
  TOP w0.201: U9.D10 160.02,90.99 149.53,90.99 148.84,90.3 v1(146.87,90.3) 146.18,90.99 R257.1 145.38,90.99 R81.2
  BOTTOM w0.201: v3(145.92,90.3) v1(146.87,90.3)
SMI_MDIO: length 17.7
  TOP w0.201: U9.D7 147.23,92.92 146.94,93.21 R75.2 145.38,94.05 145.38,94.06 R256.1
SW_BOARD_INT#: length 137.4
  TOP w0.201: YJ1.A1_2 98.03,91.62 v1(98.03,91.11) ; U1.40 135.11,130.6 134.28,129.77 134.28,128.44 137.47,125.26 140.72,125.26 141.38,125.91 C141.1 R112.1 142.38,120.73 v2(133.21,111.56)
  SIG2 w0.16: v1(98.03,91.11) 84.34,91.11 75.99,99.46 75.99,105.74 84.88,114.63 86.37,114.63 90.23,118.49 92.73,118.49 96.39,122.15 100.02,122.15 100.65,122.78 104.38,122.78 104.69,123.09 113.95,123.09 125.48,111.56 v2(133.21,111.56)
SW_BOARD_RST#: length 71.3
  TOP w0.201: v1(95.6,126.87) 95.38,126.66 95.38,123.09 101.83,116.64 YJ1.D2_2 ; R20.2 C140.1 118.68,153.88 v2(118.78,153.78)
  SIG2 w0.16: v1(95.6,126.87) 96.1,127.38 101.93,127.38 103.25,128.7 103.25,129.48 103.91,130.13 103.91,133.01 104.79,133.89 105.64,133.89 106.31,134.56 106.31,147.2 110.32,151.2 112.66,151.2 113.93,152.47 117.46,152.47 v2(118.78,153.78)
SW_DCDC_EN: length 85.4
  TOP w0.201: v2(129.66,152.83) 130.04,153.22 133.21,153.22 133.59,152.83 C139.1 R140.2 ; YJ1.D1_2 101.08,115.71 94.09,122.69 v1(94.09,126.08)
  SIG2 w0.16: v2(129.66,152.83) 128.62,151.79 115.03,151.79 113.53,150.29 110.35,150.29 106.98,146.92 106.98,134.28 105.92,133.22 105.07,133.22 104.59,132.74 104.59,131.93 105.02,131.5 105.02,129.52 102.21,126.71 96.37,126.71 95.75,126.08 v1(94.09,126.08)
SW_RESERVE1: length 27
  TOP w0.201: R321.2 R318.1 109.82,135.1 109.79,135.08 107.3,135.08 107.01,134.79 107.01,129.32 107.68,128.65 107.68,126.76 108.45,125.99 108.45,120.3 v1(109.38,119.37) 110.1,118.65 R247.2
  BOTTOM w0.201: v3(109.35,120.27) 109.35,119.4 v1(109.38,119.37)
SW_RESERVE2: length 28.4
  TOP w0.201: R248.2 109.08,114.99 109.46,115.37 109.46,117.84 v1(107.94,119.36) 107.94,125.78 107.18,126.55 107.18,128.44 106.49,129.12 106.49,135.22 107.59,136.32 109.72,136.32 109.82,136.43 R319.1 R323.2
  BOTTOM w0.201: v1(107.94,119.36) 107.95,119.37 v3(107.95,120.27)
TO_BMC_INT#: length 184.2
  TOP w0.127: U9.C37 163.14,54.79
  TOP w0.201: R121.2 108.07,133.5 v1(108.07,130.58) ; v2(145.38,65.31) R260.2 148.59,64.57 158.95,54.21 162.56,54.21 163.14,54.79
  SIG1 w0.15: v1(99.68,133.1) 99.68,132.66 103.76,128.58 104.89,128.58 105.78,129.47 106.95,129.47 v1(108.07,130.58)
  SIG2 w0.16: v2(145.38,65.31) 138.87,65.31 120.53,83.65 83.15,83.65 68.87,97.93 68.87,113.96 83.29,128.38 87.57,128.38 88.53,129.34 89.89,129.34 91.34,130.78 91.34,132.04 92.47,133.18 97.55,133.18 98.16,133.78 99,133.78 v1(99.68,133.1)
TO_CPU_INT#: length 152.8
  TOP w0.201: v1(108.98,126.79) 108.98,128.07 107.54,129.51 107.54,134.4 107.71,134.57 110.46,134.57 110.73,134.29 R116.2 ; v1(157.76,78.76) 160.75,75.77 162.53,75.77 U9.C20 ; v2(145.38,77.52) R258.2
  SIG1 w0.15: v1(157.76,78.76) 156.52,77.52 v2(145.38,77.52) 136.47,86.44 86.95,86.44 81.86,91.53 81.86,107.08 88.18,113.4 90.94,113.4 104.33,126.79 v1(108.98,126.79)
UART0_SIN: length 322.8
  TOP w0.201: U9.D1 160.65,100.54 159.74,99.62 R275.1 v2(145.38,101.4)
  SIG1 w0.15: v1(175.63,69.65) v1(175.63,56.31)
  SIG2 w0.16: J10.19 384.25,10.85 382.26,10.85 337.68,55.43 176.52,55.43 v1(175.63,56.31) ; v2(145.38,101.4) 146.01,102.03 164.07,102.03 168.9,97.21 168.9,76.38 v1(175.63,69.65)
UART0_SOUT: length 326.6
  TOP w0.201: U9.B1 163.26,101.71 146.74,101.71 146.29,102.16 R274.1 v2(145.38,102.92)
  SIG1 w0.15: v1(176.52,69.65) v1(176.52,56.31)
  SIG2 w0.16: v2(145.38,102.92) 145.76,102.54 164.33,102.54 169.41,97.46 169.41,76.76 v1(176.52,69.65) ; J10.17 385.62,11.48 382.23,11.48 337.78,55.93 176.9,55.93 v1(176.52,56.31)
USB5V: length 10.9
  TOP w0.381: J10.22 387.35,2.6 387.34,2.59 ; J10.22 387.35,4.7 ; J10.22 388.22,3.75 ; R205.1 388.1,27.99 ; J10.21 387.35,6.9 387.34,6.91 ; J10.21 388.34,5.75 ; J10.21 387.35,4.8 ; C158.2 388.1,26.85
  BOTTOM w0.381: v3(390.14,25.91) 390.02,26.03 v1(389.26,26.03) ; v1(389.26,27.94) v3(390.27,27.94) ; v1(389.26,27.05) v3(388.24,27.05)
USB_DM: length 267.6
  TOP w0.099: U9.D27 162.42,66.99 166.46,66.99 166.55,67.08 166.57,67.08
  TOP w0.183: 166.57,67.08 167.48,67.08 172.88,61.68 v1(172.88,56.31)
  SIG2 w0.099: 394.16,6.6 394.16,6.58 394.25,6.49 394.25,6.49 394.24,6.38 394.24,5.17 394.46,4.95 394.46,4.69 394.3,4.52 393.93,4.52 393.35,5.11 J10.15
  SIG2 w0.155: 394.16,6.6 394.17,6.75 394.17,7.86 388.51,13.52 382.86,13.52 339.18,57.2 172.61,57.2 172.3,56.89 172.3,56.6 172.58,56.31 v1(172.88,56.31)
USB_DP: length 267.6
  TOP w0.099: 166.57,66.69 166.55,66.69 166.46,66.78 162.03,66.78 161.9,66.64 U9.D28
  TOP w0.183: v1(171.92,56.31) 172.15,56.31 172.49,56.66 172.49,61.52 167.32,66.69 166.57,66.69
  SIG2 w0.099: 394.54,6.6 394.54,6.57 394.46,6.49 394.46,6.43 394.46,6.37 394.46,5.26 394.68,5.04 394.68,4.42 J10.14
  SIG2 w0.155: 394.54,6.6 394.55,6.75 394.55,8.02 388.67,13.9 383.02,13.9 339.33,57.58 172.46,57.58 171.92,57.05 v1(171.92,56.31)
USB_OC#: length 209.1
  TOP w0.127: U9.C29 v1(162.53,64.34)
  TOP w0.201: R125.2 126.1,153.58 v2(127.63,155.1)
  SIG2 w0.16: v1(162.53,64.34) 162.18,64 161.5,64 161.23,63.72 153.49,63.72 149.21,68 139.97,68 121.64,86.33 84.25,86.33 71.55,99.03 71.55,112.86 84.4,125.71 89.36,125.71 90.03,126.38 90.71,126.38 94.58,130.24 100.33,130.24 102.17,132.09 102.17,134.92 104.57,137.32 104.57,150.48 110.06,155.97 112.29,155.97 113.11,156.79 120.03,156.79 122.41,154.41 126.93,154.41 v2(127.63,155.1)
USB_POWER_EN: length 356.5
  TOP w0.201: v2(385.19,32.26) 385.9,31.55 394.71,31.55 394.99,31.27 R209.2 394.2,30.79 394.13,30.72 U5.3 ; R124.2 124.96,153.83 v1(126.23,155.1)
  SIG1 w0.15: v1(175.96,124.87) 178.39,122.43 v1(178.39,102.42) ; v1(146.04,145.34) 146.04,147.37 137.78,155.63 126.75,155.63 v1(126.23,155.1)
  SIG2 w0.16: v1(178.39,102.42) 178.93,101.88 178.93,75.6 184.94,69.59 345.23,69.59 383.02,31.8 384.74,31.8 v2(385.19,32.26) ; v1(175.96,124.87) 155.01,145.82 146.52,145.82 v1(146.04,145.34)
USB_POWER_OC#: length 351
  TOP w0.201: R208.2 v2(385.16,30.79) ; v1(125.34,155.1) 124.42,154.19 124.42,151.54 124.09,151.21 R122.1 123.81,149.53 123.97,149.38 U1.94
  SIG1 w0.15: v1(145.13,145.34) 145.13,146.87 136.94,155.06 129.22,155.06 128.64,154.49 125.96,154.49 v1(125.34,155.1) ; v1(175.99,123.09) 176.49,123.09 177.89,121.69 177.89,101.15 v1(178.39,100.64)
  SIG2 w0.16: v1(145.13,145.34) 145.13,145.95 145.4,146.22 155.26,146.22 176.44,125.04 176.44,123.55 v1(175.99,123.09) ; v2(385.16,30.79) 383.41,30.79 345.05,69.14 184.47,69.14 178.39,75.22 v1(178.39,100.64)
USB_RX_N: length 24.5
  TOP w0.183: R87.1 145.76,86.48 146.32,86.48 v1(146.63,86.17) ; U9.A12 v1(166.34,87.2)
  SIG1 w0.142: v1(146.63,86.17) 147.01,86.54 149.13,86.54 149.99,85.68 165.05,85.68 165.85,86.48 165.85,87.48 166.03,87.66 166.23,87.66 166.34,87.55 v1(166.34,87.2)
USB_RX_P: length 24.5
  TOP w0.183: v1(146.63,87.18) 146.3,86.85 145.78,86.85 R69.1 ; U9.A11 v1(166.34,88.47)
  SIG1 w0.142: v1(146.63,87.18) 146.92,86.9 149.28,86.9 150.14,86.03 164.9,86.03 165.49,86.63 165.49,87.62 165.88,88.01 166.27,88.01 166.34,88.08 v1(166.34,88.47)
VR_EN: length 231.6
  TOP w0.201: U9.D30 155.95,63.71 150.26,69.4 R276.1 v1(145.38,68.66) ; R145.2 138.83,153.06 138.04,153.85 v2(134.48,153.85)
  SIG1 w0.15: v1(145.38,68.66) 139.26,62.54 J11.2
  SIG2 w0.16: v1(145.38,68.66) 144.52,69.52 139.18,69.52 121.97,86.73 98.17,86.73 96.55,88.35 82.8,88.35 71.95,99.2 71.95,112.69 84.56,125.31 89.53,125.31 90.2,125.98 90.88,125.98 94.74,129.84 100.49,129.84 102.57,131.92 102.57,134.75 104.97,137.15 104.97,150.31 110.23,155.57 112.45,155.57 113.27,156.39 118.92,156.39 120.25,155.06 121.19,155.06 122.24,154.01 134.32,154.01 v2(134.48,153.85)
N17108255: length 3.7
  TOP w0.201: R16.1 112.51,138.48 112.63,138.6 v1(113.67,138.6) U1.125
  BOTTOM w0.201: v3(112.9,138.56) 113.62,138.56 v1(113.67,138.6)
N17108932: length 8.2
  TOP w0.201: v1(109.22,130.56) 109.57,130.9 R4.1 109.57,131.47 109.79,131.7 113.17,131.7 114.07,132.6 U1.137
  BOTTOM w0.201: v3(108.97,129.41) 108.97,130.3 v1(109.22,130.56)
N17120577: length 5.8
  TOP w0.201: v1(116.33,141.1) v3(115.02,141.1) 114.24,141.1 113.65,140.52 R17.1
  BOTTOM w0.201: v3(115.02,141.1) v1(116.33,141.1)
N17132235: length 7.8
  TOP w0.201: J7.1 28.56,88.95 v1(33.27,88.95) R48.2
  BOTTOM w0.201: v1(33.27,88.95) 33.35,89.03 v3(34.16,89.03)
N17132359: length 7.8
  TOP w0.201: R49.2 v1(33.4,93.02) 28.82,93.02 J7.5
  BOTTOM w0.201: v1(33.4,93.02) 33.45,92.96 v3(34.16,92.96)
N17132366: length 25.4
  TOP w0.201: J7.9 27.04,97.59 24.88,97.59 24.5,97.21 24.5,92.64 24.75,92.38 26.41,92.38 27.04,91.75 27.04,87.43 27.93,86.54 v1(33.27,86.54) R51.2
  BOTTOM w0.201: v1(33.27,86.54) 33.33,86.49 v3(34.29,86.49)
N17497473: length 13.7
  TOP w0.201: J2.14 316.4,167.29 v1(324.1,167.29) R311.1 R98.1 R278.1
  BOTTOM w0.201: v3(325.12,167.26) 324.13,167.26 v1(324.1,167.29)
N17497957: length 5.5
  TOP w0.201: R101.2 R282.2 236.21,167.19 236.15,167.13 v3(235.07,167.13) 233.93,167.13 v1(233.81,167)
  BOTTOM w0.201: v3(235.07,167.13) 233.93,167.13 v1(233.81,167)
N17498397: length 32.8
  TOP w0.201: R284.1 R104.1 100.95,158.3 101.21,158.55 R313.1 104.41,160.05 v2(103.41,161.05)
  SIG2 w0.16: J5.14 119.77,163.5 107.09,163.5 104.64,161.05 v2(103.41,161.05)
N17503631: length 2.9
  TOP w0.201: R54.1 129.28,124.72 128.97,125.02 U1.25
N17503838: length 3
  TOP w0.201: R327.1 132.07,125.53 132.47,125.93 U1.32
N17504179: length 4.2
  TOP w0.201: R6.1 v1(123.56,125.07) 122.97,125.66 U1.13
  BOTTOM w0.201: v3(123.57,126.24) 123.57,125.08 v1(123.56,125.07)
N17504817: length 4.1
  TOP w0.201: R326.1 125.97,124.37 125.97,124.7 v1(126.37,125.09) 125.97,125.49 U1.19
  BOTTOM w0.201: v1(126.37,125.09) 126.62,124.84 v3(126.62,124.21)
N17504991: length 3
  TOP w0.201: U1.5 118.97,126.4 118.61,126.04 118.61,125.02 118.48,124.89 R31.1
N17510509: length 5.2
  TOP w0.201: v1(118.47,147.21) U1.105 118.47,150.31 118.1,150.68 R20.1
  BOTTOM w0.201: v1(118.47,147.21) 119.08,147.83 v3(119.25,147.83)
N17540351: length 9.5
  TOP w0.201: v1(117.22,141.1) 116.72,141.6 116.55,141.6 116.54,141.6 115.1,141.6 115.09,141.6 U1.119 114.1,141.6 113.86,141.35 109.66,141.35 109.44,141.58 R89.1
  BOTTOM w0.201: v3(118.24,141.1) v1(117.22,141.1)
N17565545: length 3.2
  TOP w0.201: U1.3 117.97,125.44 117.08,124.55 R325.1
N17614810: length 12
  TOP w0.201: R96.2 329.55,167.69 v1(329.14,168.11) 328.77,168.48 324.28,168.48 321.81,170.95 J2.1
  BOTTOM w0.201: v1(329.14,168.11) 329.06,168.02 v3(329.06,167.13)
N17614841: length 19.1
  TOP w0.201: R99.2 v1(242.03,170) 241.08,170.95 J4.1
  BOTTOM w0.201: v1(242.03,170) 241.55,169.53 v3(241.55,169.29)
N17614872: length 36.8
  TOP w0.201: v2(104.31,162.16) R102.2
  SIG2 w0.16: J5.1 128.28,169.47 123.81,169.47 123.18,168.84 123.18,167.57 119.55,163.94 106.66,163.94 104.88,162.16 v2(104.31,162.16)
N17614948: length 21.5
  TOP w0.201: J4.3 221.08,169.85 227.83,169.85 228.42,170.44 238.54,170.44 238.9,170.08 v1(238.9,169.93) R100.2
  BOTTOM w0.201: v3(239.38,169.22) 239.38,169.44 v1(238.9,169.93)
N17614979: length 33.9
  TOP w0.201: v2(104.26,163.5) 108.83,158.93 110.1,158.93 111.24,157.79 R103.2
  SIG2 w0.16: v2(104.26,163.5) 105.49,164.74 117.56,164.74 121.02,168.2 121.02,169.09 121.71,169.78 123.51,169.78 J5.3
N17615052: length 16
  TOP w0.201: R97.2 328.54,167.57 328.13,167.98 v1(327.28,167.98) 322.92,167.98 321.3,169.6 316.63,169.6 J2.3
  BOTTOM w0.201: v3(327.03,167) 327.03,167.72 v1(327.28,167.98)
N17711157: length 8.4
  TOP w0.201: J8.B19 376.94,127.11 376.94,124.08 375.97,123.11 R172.1
N17711159: length 8.3
  TOP w0.201: J8.B20 374.42,127.14 374.42,123.95 374.07,123.6 374.07,122.15 373.68,121.77 R173.1
N17711235: length 9.5
  TOP w0.201: J9.B22 13.08,127.18 13.08,124.97 10.29,122.17 10.03,122.17 9.58,121.72 R185.1
N17711333: length 8
  TOP w0.201: J9.B20 18.16,127.18 18.16,122.2 18.34,122.02 R182.1
N17711335: length 8
  TOP w0.201: R181.1 21.01,121.64 20.73,121.92 20.73,127.2 J9.B19
N17711436: length 10.6
  TOP w0.201: R176.1 365.18,121.72 366.27,122.81 367.67,122.81 369.34,124.49 369.34,127.14 J8.B22
N17755002: length 5.8
  TOP w0.201: J8.A25 360.86,123.73 R178.2
N17758888: length 12.1
  TOP w0.201: R175.2 365.66,118.06 v1(365.94,118.34) 366.27,118.67 366.27,121.79 366.78,122.3 367.94,122.3 370.66,125.03 J8.A22
  BOTTOM w0.201: v1(365.94,118.34) 366.01,118.26 v3(366.01,117.35)
N17770839: length 5.1
  TOP w0.201: J9.A25 7.42,125.24 R187.2
N17770842: length 6.3
  TOP w0.201: R184.2 10.72,121.72 14.36,125.36 J9.A22
N17771627: length 11.2
  TOP w0.201: J8.B24 364.4,127.27 362.23,127.27 359.71,124.76 R177.1
N17771650: length 10.6
  TOP w0.201: J9.B24 8.01,127.19 5.9,127.19 5.33,126.62 5.33,124.46 6.27,123.52 R186.1
N17785334: length 2.9
  TOP w0.381: C102.2 398.41,58.12
  TOP w0.559: U4.2 397.88,55.17 397.63,55.43
N17785336: length 3.2
  TOP w0.381: R202.1 402.05,58.12 402.45,57.71 402.45,56.5 402.07,56.12 U4.6
N17785348: length 6.1
  TOP w0.381: R207.1 R204.2 404.38,53.75 404.64,54 C103.2 404.05,54.66 403.61,54.22 U4.4
N17785528: length 1.7
  TOP w0.381: R202.2 C102.1
N17786050: length 2.7
  TOP w0.381: C91.2 404.23,39.8
  TOP w0.559: 402.33,42.34 401.82,42.85 U3.2
N17786052: length 4.3
  TOP w0.381: R192.1 397.84,39.8 397.51,40.13 v1(397.51,40.89) 397.51,41.57 397.85,41.9 U3.6
  BOTTOM w0.381: v3(396.62,40.89) v1(397.51,40.89)
N17786060: length 5.6
  TOP w0.381: C92.2 397.25,44.25 397.69,43.8 U3.4
  TOP w0.508: R201.2 R195.2 396.2,45.11 395.95,44.86 C92.2
N17786072: length 1.7
  TOP w0.381: R192.2 C91.1
N17795988: length 8
  TOP w0.381: R200.2 R199.2 C101.2 411.22,51.11 410.83,50.73 408.55,50.73 407.86,51.42 Q8.1
N17796014: length 6.3
  TOP w0.381: R197.1 R196.2 410.49,57.18 410.14,56.82 410.14,54.85 409.69,54.41 Q8.3
N17796016: length 1.9
  TOP w0.381: Q7.1 411.57,59.36 R197.2
N17801552: length 2.1
  TOP w0.201: U5.4 388.17,30.72 388.1,30.79 R208.1
N17801562: length 2.5
  TOP w0.201: U5.5 387.85,29.77 387.47,29.39 R206.1
N17812600: length 10.8
  TOP w0.201: R171.1 v1(33.4,95.18) 33.14,95.18 33.01,95.3 29.58,95.3 29.07,94.8 26.79,94.8 J7.6
  BOTTOM w0.201: v1(33.4,95.18) 33.45,95.12 v3(34.16,95.12)
N17823833: length 2.5
  TOP w0.508: D3.1 R194.2
N17824733: length 5.5
  TOP w0.201: v1(114.94,155.45) 115.66,156.17 D1.1 116.58,156.77 117.44,157.63 R119.2
  BOTTOM w0.201: v3(114.81,154.43) 114.81,155.32 v1(114.94,155.45)
N17825329: length 3.9
  TOP w0.201: R124.1 124.96,150.68 124.47,150.19 v1(124.47,149.73) U1.93
  BOTTOM w0.201: v3(124.71,148.84) 124.71,149.49 v1(124.47,149.73)
N17852949: length 5.4
  TOP w0.201: R157.1 122.54,125.4 122.47,125.48 U1.12 v1(122.47,128.61)
  BOTTOM w0.201: v1(122.47,128.61) 122.25,128.83 v3(121.47,128.83)
N17861782: length 4.5
  TOP w0.201: R222.1 R220.1 153.82,171.55 v1(153.72,171.66) U7.7
  BOTTOM w0.201: v3(152.91,171.7) 153.67,171.7 v1(153.72,171.66)
N17861792: length 5
  TOP w0.201: U7.6 153.28,170.39 v1(153.64,170.02) 154.15,169.52 R224.1 R223.1
  BOTTOM w0.201: v3(152.78,170.31) 153.36,170.31 v1(153.64,170.02)
N17861802: length 7.4
  TOP w0.201: U7.5 v1(153.59,169.12) 154.2,168.5 R225.1 154.74,167.95 154.86,167.82 156.96,167.82 157.11,167.97 R226.1
  BOTTOM w0.201: v1(153.59,169.12) 153.51,169.04 v3(152.65,169.04)
N17861847: length 3.5
  TOP w0.201: U7.1 v1(144.65,172.93) 143.66,172.93 R219.2
  BOTTOM w0.201: v1(144.65,172.93) 144.7,172.97 v3(145.42,172.97)
N17862775: length 3.7
  TOP w0.201: U7.3 v1(144.91,170.39) 143.66,170.39 R221.2
  BOTTOM w0.201: v3(144.91,169.42) v1(144.91,170.39)
N17864736: length 5.9
  TOP w0.201: R244.2 R241.2 100.95,153.06 v1(100.45,152.56) 99.32,151.43 U8.1
  BOTTOM w0.201: v3(100.48,151.54) 100.48,152.53 v1(100.45,152.56)
N17864738: length 5.2
  TOP w0.201: U8.21 97.37,144.07 97.12,143.81 96.38,143.81 95.92,143.35 v2(95.92,142.89) 96.41,142.39 R243.2 R246.2
N17864740: length 6
  TOP w0.201: U8.2 98.67,151.67 99.56,152.55 v1(99.56,152.65) 99.56,152.83 98.92,153.47 R245.2 R242.2
  BOTTOM w0.201: v1(99.56,152.65) 99.57,152.66 v3(99.57,153.8)
N17865867: length 2.5
  TOP w0.201: U8.23 98.67,142.64 R239.2
N17879948: length 3.8
  TOP w0.201: U2.7 65.44,88.28 v1(65.78,87.94) R155.1
  BOTTOM w0.201: v1(65.78,87.94) 65.72,87.88 v3(64.9,87.88)
N17880008: length 13.8
  TOP w0.201: U2.18 v1(60.21,85.68) 62.16,87.63 62.16,90.91 62.49,91.24 R146.1
  BOTTOM w0.201: v1(60.21,85.68) 60.17,85.72 v3(59.18,85.72)
N17880012: length 13.5
  TOP w0.201: R147.1 62.59,92.76 61.15,91.33 61.15,88.31 59.82,86.98 v1(59.44,86.98) U2.16
  BOTTOM w0.201: v3(60.33,86.99) 59.45,86.99 v1(59.44,86.98)
N17880028: length 14
  TOP w0.201: R148.1 63.57,95.18 60.14,91.75 60.14,88.78 59.64,88.28 v1(59.18,88.28) U2.14
  BOTTOM w0.201: v3(58.29,88.26) 59.17,88.26 v1(59.18,88.28)
N17880056: length 13.9
  TOP w0.201: R149.1 63.79,96.83 59.12,92.16 v1(59.12,89.73) 58.97,89.58 U2.12
  BOTTOM w0.201: v1(59.12,89.73) 59.18,89.79 v3(60.07,89.79)
N17880058: length 3.7
  TOP w0.201: R151.1 v1(65.76,85.78) 65.08,85.78 64.98,85.68 U2.3
  BOTTOM w0.201: v1(65.76,85.78) 65.69,85.85 v3(64.9,85.85)
N17880102: length 3.9
  TOP w0.201: U2.5 64.7,86.98 64.89,86.79 v1(65.76,86.79) R152.1
  BOTTOM w0.201: v1(65.76,86.79) 65.81,86.74 v3(66.8,86.74)
